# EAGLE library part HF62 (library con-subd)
SUB-D
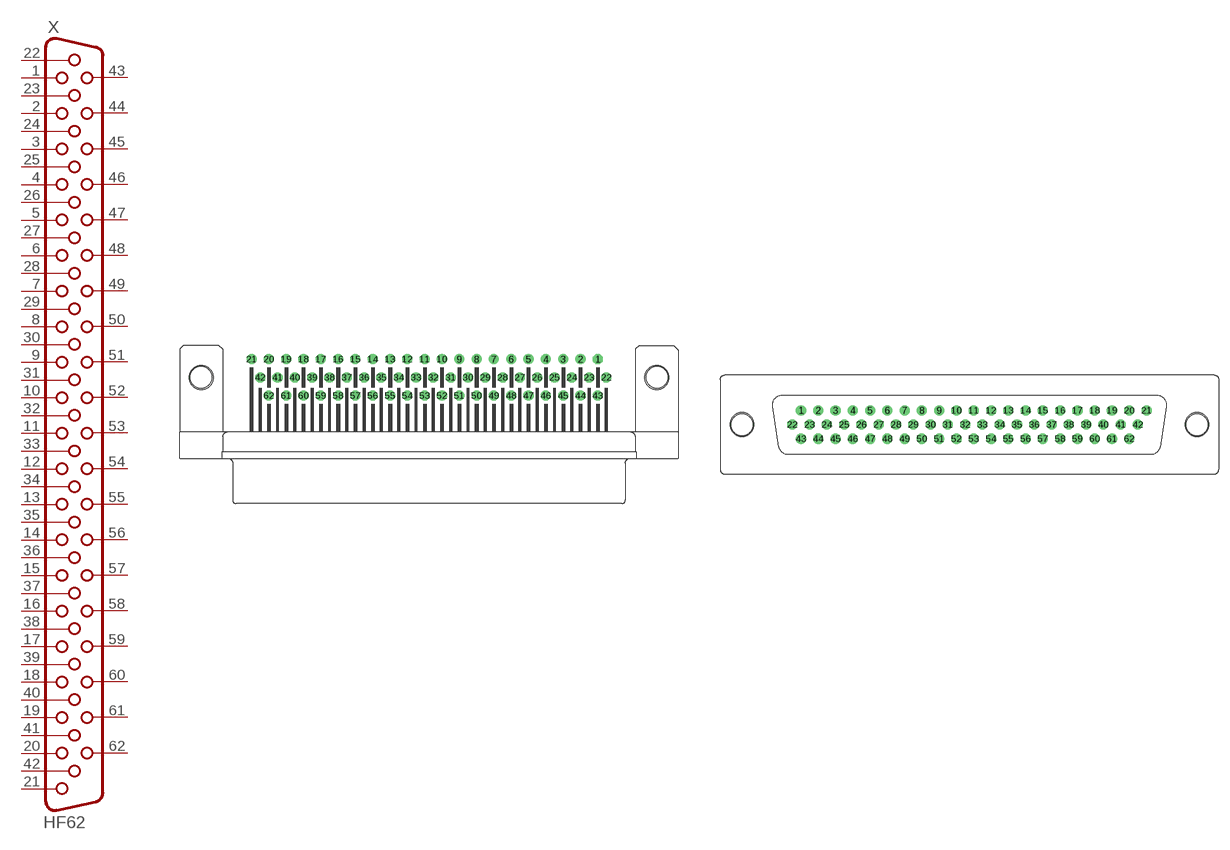
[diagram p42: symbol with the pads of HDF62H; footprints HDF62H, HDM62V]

Designator prefix X

## HF62H (OC_FARNELL: unknown; OC_NEWARK: unknown)  [HDF62H]
1  1  pas
2  2  pas
3  3  pas
4  4  pas
5  5  pas
6  6  pas
7  7  pas
8  8  pas
9  9  pas
10  10  pas
11  11  pas
12  12  pas
13  13  pas
14  14  pas
15  15  pas
16  16  pas
17  17  pas
18  18  pas
19  19  pas
20  20  pas
21  21  pas
22  22  pas
23  23  pas
24  24  pas
25  25  pas
26  26  pas
27  27  pas
28  28  pas
29  29  pas
30  30  pas
31  31  pas
32  32  pas
33  33  pas
34  34  pas
35  35  pas
36  36  pas
37  37  pas
38  38  pas
39  39  pas
40  40  pas
41  41  pas
42  42  pas
43  43  pas
44  44  pas
45  45  pas
46  46  pas
47  47  pas
48  48  pas
49  49  pas
50  50  pas
51  51  pas
52  52  pas
53  53  pas
54  54  pas
55  55  pas
56  56  pas
57  57  pas
58  58  pas
59  59  pas
60  60  pas
61  61  pas
62  62  pas

## HF62V (OC_FARNELL: unknown; OC_NEWARK: unknown)  [HDM62V]
Pads as for HDF62H

## Footprint HDF62H (pad centres in mm)
SUB-D
drill 0.9 octagon: 1 23.527,2.54
drill 0.9 round: 2 21.114,2.54; 3 18.701,2.54; 4 16.288,2.54; 5 13.875,2.54; 6 11.462,2.54; 7 9.049,2.54; 8 6.636,2.54; 9 4.223,2.54; 10 1.81,2.54; 11 -0.603,2.54; 12 -3.016,2.54; 13 -5.429,2.54; 14 -7.842,2.54; 15 -10.255,2.54; 16 -12.668,2.54; 17 -15.081,2.54; 18 -17.494,2.54; 19 -19.907,2.54; 20 -22.32,2.54; 21 -24.733,2.54; 22 24.734,0; 23 22.321,0; 24 19.908,0; 25 17.495,0; 26 15.082,0; 27 12.669,0; 28 10.256,0; 29 7.843,0; 30 5.43,0; 31 3.017,0; 32 0.604,0; 33 -1.809,0; 34 -4.222,0; 35 -6.635,0; 36 -9.048,0; 37 -11.461,0; 38 -13.874,0; 39 -16.287,0; 40 -18.7,0; 41 -21.113,0; 42 -23.526,0; 43 23.527,-2.54; 44 21.114,-2.54; 45 18.701,-2.54; 46 16.288,-2.54; 47 13.875,-2.54; 48 11.462,-2.54; 49 9.049,-2.54; 50 6.636,-2.54; 51 4.223,-2.54; 52 1.81,-2.54; 53 -0.603,-2.54; 54 -3.016,-2.54; 55 -5.429,-2.54; 56 -7.842,-2.54; 57 -10.255,-2.54; 58 -12.668,-2.54; 59 -15.081,-2.54; 60 -17.494,-2.54; 61 -19.907,-2.54; 62 -22.32,-2.54
hole 3 at -31.75,0
hole 3 at 31.75,0

## Footprint HDM62V (pad centres in mm)
SUB-D
drill 0.9 round: 1 -23.532,1.98; 2 -21.119,1.98; 3 -18.706,1.98; 4 -16.293,1.98; 5 -13.88,1.98; 6 -11.467,1.98; 7 -9.054,1.98; 8 -6.641,1.98; 9 -4.228,1.98; 10 -1.815,1.98; 11 0.598,1.98; 12 3.011,1.98; 13 5.424,1.98; 14 7.837,1.98; 15 10.25,1.98; 16 12.663,1.98; 17 15.076,1.98; 18 17.489,1.98; 19 19.902,1.98; 20 22.315,1.98; 21 24.728,1.98; 22 -24.739,0; 23 -22.325,0; 24 -19.912,0; 25 -17.499,0; 26 -15.086,0; 27 -12.673,0; 28 -10.26,0; 29 -7.847,0; 30 -5.434,0; 31 -3.021,0; 32 -0.608,0; 33 1.805,0; 34 4.218,0; 35 6.631,0; 36 9.044,0; 37 11.457,0; 38 13.87,0; 39 16.283,0; 40 18.696,0; 41 21.109,0; 42 23.522,0; 43 -23.532,-1.98; 44 -21.119,-1.98; 45 -18.706,-1.98; 46 -16.293,-1.98; 47 -13.88,-1.98; 48 -11.467,-1.98; 49 -9.054,-1.98; 50 -6.641,-1.98; 51 -4.228,-1.98; 52 -1.815,-1.98; 53 0.598,-1.98; 54 3.011,-1.98; 55 5.424,-1.98; 56 7.837,-1.98; 57 10.25,-1.98; 58 12.663,-1.98; 59 15.076,-1.98; 60 17.489,-1.98; 61 19.902,-1.98; 62 22.315,-1.98
hole 3 at -31.75,0
hole 3 at 31.75,0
